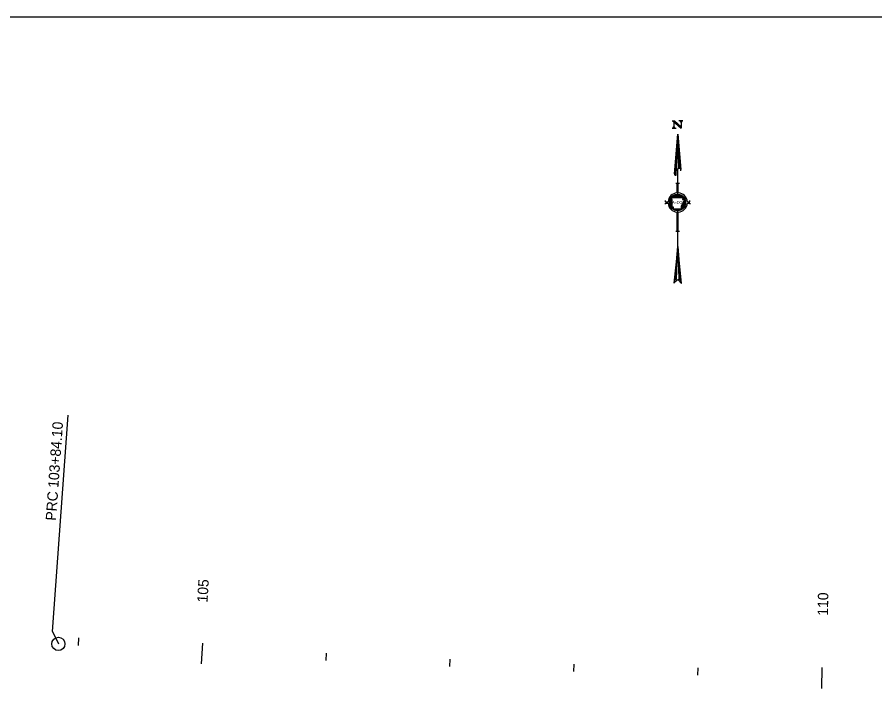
# Model space of a CAD drawing. Extents: x 1806834 to 1810084, y 678065 to 679314.
# Drawn here: x 1807616 to 1808308, y 678514 to 679065 of the extents above; entities that cross this region are included whole.
import ezdxf

# ---------------------------------------------------------------- set-up
doc = ezdxf.new("R2010")
doc.units = 0
for name, color, linetype in [('Default', 7, 'Continuous'), ('DSN_DRFT_Guideline-No-Plot', 7, 'Continuous'), ('DSN_RDWY_Alignment Annotation', 7, 'Continuous')]:
    doc.layers.add(name, color=color, linetype=linetype)

msp = doc.modelspace()

# ---------------------------------------------------------------- linework, layer by layer
at = {"layer": 'Default'}
for p, q in [((1808144.25, 678980.98), (1808146.02, 678980.98)), ((1808144.79, 678980.98), (1808151.47, 678975.04)), ((1808144.87, 678980.98), (1808151.47, 678975.12)), ((1808144.95, 678980.98), (1808151.47, 678975.17)), ((1808145.02, 678980.98), (1808151.47, 678975.25)), ((1808145.1, 678980.98), (1808151.47, 678975.3)), ((1808145.18, 678980.98), (1808151.47, 678975.38)), ((1808145.23, 678980.98), (1808151.47, 678975.43)), ((1808145.3, 678980.98), (1808151.47, 678975.5)), ((1808145.38, 678980.98), (1808151.47, 678975.56)), ((1808145.46, 678980.98), (1808151.47, 678975.63)), ((1808145.54, 678980.98), (1808151.47, 678975.71)), ((1808145.61, 678980.98), (1808151.47, 678975.76)), ((1808145.64, 678980.98), (1808145.64, 678975.04)), ((1808145.69, 678980.98), (1808151.47, 678975.84)), ((1808145.74, 678980.98), (1808151.47, 678975.89)), ((1808145.82, 678980.98), (1808151.47, 678975.97)), ((1808145.9, 678980.98), (1808151.47, 678976.02)), ((1808145.97, 678980.98), (1808151.47, 678976.1)), ((1808146.02, 678980.98), (1808151.47, 678976.12)), ((1808151.08, 678980.98), (1808149.59, 678980.98)), ((1808152.83, 678980.98), (1808151.08, 678980.98)), ((1808151.47, 678980.98), (1808151.47, 678975.04)), ((1808144.25, 678975.04), (1808146.02, 678975.04)), ((1808146.02, 678975.04), (1808147.51, 678975.04)), ((1808146.25, 678937.53), (1808146.25, 678938.3)), ((1808146.64, 678937.22), (1808146.64, 678939.07)), ((1808147, 678937.15), (1808147, 678939.61)), ((1808147.46, 678937.15), (1808147.46, 678940.77)), ((1808148.64, 678921.99), (1808148.64, 678941.93)), ((1808147.18, 678930.7), (1808148.16, 678930.7)), ((1808148.16, 678922.94), (1808148.16, 678930.7)), ((1808149.13, 678922.97), (1808149.13, 678930.7)), ((1808149.13, 678930.7), (1808150.11, 678930.7)), ((1808138.91, 678915.67), (1808138.91, 678916.65)), ((1808138.91, 678915.67), (1808140.87, 678915.67)), ((1808142.07, 678913.54), (1808142.07, 678916.77)), ((1808142.3, 678912.77), (1808142.3, 678917.52)), ((1808142.56, 678912.25), (1808142.56, 678918.08)), ((1808142.79, 678911.84), (1808142.79, 678918.52)), ((1808143.04, 678911.46), (1808143.04, 678918.91)), ((1808143.27, 678911.1), (1808143.27, 678919.29)), ((1808143.53, 678910.86), (1808143.53, 678919.6)), ((1808143.76, 678910.58), (1808143.76, 678919.83)), ((1808144.3, 678916.18), (1808143.84, 678919.16)), ((1808143.84, 678919.16), (1808152.73, 678919.16)), ((1808144.02, 678919.16), (1808144.02, 678920.09)), ((1808144.02, 678910.33), (1808144.02, 678917.93)), ((1808144.1, 678911.69), (1808144.3, 678916.18)), ((1808144.25, 678919.16), (1808144.25, 678920.29)), ((1808144.25, 678915.64), (1808144.25, 678916.31)), ((1808144.51, 678919.16), (1808144.51, 678920.52)), ((1808144.74, 678919.16), (1808144.74, 678920.7)), ((1808145, 678919.16), (1808145, 678920.86)), ((1808145.23, 678919.16), (1808145.23, 678921.01)), ((1808145.48, 678919.16), (1808145.48, 678921.14)), ((1808145.72, 678919.16), (1808145.72, 678921.27)), ((1808145.97, 678919.16), (1808145.97, 678921.37)), ((1808146.2, 678919.16), (1808146.2, 678921.48)), ((1808146.44, 678919.16), (1808146.44, 678921.58)), ((1808146.69, 678919.16), (1808146.69, 678921.65)), ((1808146.92, 678919.16), (1808146.92, 678921.73)), ((1808147.18, 678919.16), (1808147.18, 678921.78)), ((1808147.41, 678919.16), (1808147.41, 678921.84)), ((1808147.67, 678919.16), (1808147.67, 678921.86)), ((1808147.9, 678919.16), (1808147.9, 678921.91)), ((1808148.16, 678919.16), (1808148.16, 678921.94)), ((1808148.39, 678919.16), (1808148.39, 678921.96)), ((1808148.64, 678919.16), (1808148.64, 678921.99)), ((1808148.88, 678919.16), (1808148.88, 678921.94)), ((1808149.13, 678919.16), (1808149.13, 678921.94)), ((1808149.36, 678919.16), (1808149.36, 678921.89)), ((1808149.62, 678919.16), (1808149.62, 678921.86)), ((1808149.85, 678919.16), (1808149.85, 678921.81)), ((1808150.11, 678919.16), (1808150.11, 678921.76)), ((1808150.34, 678919.16), (1808150.34, 678921.71)), ((1808150.57, 678919.16), (1808150.57, 678921.63)), ((1808150.83, 678919.16), (1808150.83, 678921.55)), ((1808151.06, 678919.16), (1808151.06, 678921.48)), ((1808151.32, 678919.16), (1808151.32, 678921.37)), ((1808151.55, 678919.16), (1808151.55, 678921.27)), ((1808151.8, 678919.16), (1808151.8, 678921.14)), ((1808152.04, 678919.16), (1808152.04, 678921.01)), ((1808152.29, 678919.16), (1808152.29, 678920.86)), ((1808152.52, 678919.16), (1808152.52, 678920.68)), ((1808152.88, 678918.37), (1808152.55, 678917.67)), ((1808152.55, 678917.67), (1808154.07, 678917.67)), ((1808152.73, 678919.16), (1808152.73, 678919.16)), ((1808152.73, 678919.16), (1808152.93, 678918.8)), ((1808152.78, 678919.11), (1808152.78, 678920.52)), ((1808152.78, 678917.67), (1808152.78, 678918.11)), ((1808152.93, 678918.8), (1808152.88, 678918.37)), ((1808153.01, 678917.7), (1808153.01, 678920.29)), ((1808153.47, 678915.9), (1808153.19, 678915.1)), ((1808153.27, 678917.7), (1808153.27, 678920.11)), ((1808153.47, 678915.9), (1808153.73, 678916.54)), ((1808153.5, 678917.7), (1808153.5, 678919.86)), ((1808153.5, 678910.5), (1808153.5, 678915.93)), ((1808154.17, 678917.08), (1808153.73, 678916.54)), ((1808153.76, 678917.67), (1808153.76, 678919.6)), ((1808153.76, 678910.76), (1808153.76, 678916.54)), ((1808153.99, 678917.67), (1808153.99, 678919.34)), ((1808153.99, 678911.07), (1808153.99, 678916.85)), ((1808154.07, 678917.67), (1808154.27, 678917.42)), ((1808154.27, 678917.42), (1808154.17, 678917.08)), ((1808154.25, 678917.49), (1808154.25, 678918.98)), ((1808154.25, 678911.4), (1808154.25, 678917.24)), ((1808154.48, 678911.76), (1808154.48, 678918.57)), ((1808154.71, 678912.23), (1808154.71, 678918.14)), ((1808154.96, 678912.79), (1808154.96, 678917.57)), ((1808155.2, 678913.61), (1808155.2, 678916.8)), ((1808156.41, 678915.67), (1808158.36, 678915.67)), ((1808158.36, 678915.67), (1808158.36, 678916.65)), ((1808138.91, 678913.72), (1808138.91, 678914.69)), ((1808138.91, 678914.69), (1808140.87, 678914.69)), ((1808144.48, 678911.46), (1808144.1, 678911.69)), ((1808144.25, 678910.12), (1808144.25, 678911.56)), ((1808145.23, 678911.46), (1808144.48, 678911.46)), ((1808144.51, 678909.91), (1808144.51, 678911.43)), ((1808144.74, 678909.71), (1808144.74, 678911.43)), ((1808145, 678909.58), (1808145, 678911.43)), ((1808145.23, 678909.86), (1808145.23, 678911.46)), ((1808151.44, 678909.86), (1808145.23, 678909.86)), ((1808145.23, 678909.4), (1808145.23, 678909.84)), ((1808145.48, 678909.27), (1808145.48, 678909.86)), ((1808145.72, 678909.14), (1808145.72, 678909.86)), ((1808145.97, 678909.04), (1808145.97, 678909.86)), ((1808146.2, 678908.94), (1808146.2, 678909.86)), ((1808146.44, 678908.84), (1808146.44, 678909.86)), ((1808146.69, 678908.76), (1808146.69, 678909.86)), ((1808146.92, 678908.68), (1808146.92, 678909.86)), ((1808147.18, 678908.63), (1808147.18, 678909.86)), ((1808147.41, 678908.55), (1808147.41, 678909.86)), ((1808147.67, 678908.53), (1808147.67, 678909.86)), ((1808147.9, 678908.5), (1808147.9, 678909.86)), ((1808148.16, 678908.45), (1808148.16, 678909.86)), ((1808148.39, 678908.42), (1808148.39, 678909.86)), ((1808148.64, 678908.42), (1808148.64, 678909.86)), ((1808148.88, 678908.42), (1808148.88, 678909.86)), ((1808149.13, 678908.45), (1808149.13, 678909.86)), ((1808149.36, 678908.48), (1808149.36, 678909.86)), ((1808149.62, 678908.5), (1808149.62, 678909.86)), ((1808149.85, 678908.55), (1808149.85, 678909.86)), ((1808150.11, 678908.6), (1808150.11, 678909.86)), ((1808150.34, 678908.66), (1808150.34, 678909.86)), ((1808150.57, 678908.73), (1808150.57, 678909.86)), ((1808150.83, 678908.78), (1808150.83, 678909.86)), ((1808151.06, 678908.89), (1808151.06, 678909.86)), ((1808151.32, 678908.99), (1808151.32, 678909.86)), ((1808151.75, 678910.5), (1808151.44, 678909.86)), ((1808151.55, 678909.09), (1808151.55, 678909.99)), ((1808151.8, 678912.74), (1808151.65, 678911.56)), ((1808151.65, 678911.56), (1808151.75, 678910.5)), ((1808152.34, 678913.67), (1808151.8, 678912.74)), ((1808151.8, 678909.22), (1808151.8, 678912.53)), ((1808152.04, 678909.35), (1808152.04, 678913.05)), ((1808152.29, 678909.5), (1808152.29, 678913.49)), ((1808152.68, 678914.36), (1808152.34, 678913.67)), ((1808152.52, 678909.66), (1808152.52, 678913.97)), ((1808153.19, 678915.1), (1808152.68, 678914.36)), ((1808152.78, 678909.84), (1808152.78, 678914.44)), ((1808153.01, 678910.04), (1808153.01, 678914.8)), ((1808153.27, 678910.25), (1808153.27, 678915.28)), ((1808156.41, 678914.69), (1808158.36, 678914.69)), ((1808158.36, 678914.69), (1808158.36, 678913.72)), ((1808148.16, 678892.14), (1808148.16, 678907.42)), ((1808148.64, 678879.67), (1808148.64, 678908.37)), ((1808149.13, 678892.14), (1808149.13, 678907.42)), ((1808147.18, 678892.14), (1808148.16, 678892.14)), ((1808149.13, 678892.14), (1808150.11, 678892.14)), ((1808148.64, 678879.67), (1808145.58, 678850.16)), ((1808151.61, 678849.93), (1808148.64, 678879.67)), ((1808145.58, 678850.16), (1808148.64, 678853.21)), ((1808148.64, 678853.21), (1808151.61, 678849.93))]:
    msp.add_line(p, q, dxfattribs=at)
for points in [[(1808152.29, 678980.98), (1808151.47, 678979.95), (1808150.67, 678980.98), (1808150.8, 678980.93), (1808152.19, 678980.93), (1808151.47, 678980.03), (1808150.83, 678980.87), (1808152.11, 678980.9), (1808151.47, 678980.13), (1808150.93, 678980.82), (1808151.98, 678980.85), (1808151.47, 678980.21), (1808151.03, 678980.77), (1808151.86, 678980.8), (1808151.47, 678980.31), (1808151.16, 678980.72), (1808151.75, 678980.75), (1808151.47, 678980.39), (1808151.27, 678980.67), (1808151.62, 678980.69), (1808151.47, 678980.46), (1808151.37, 678980.64), (1808151.52, 678980.64), (1808151.47, 678980.54), (1808151.44, 678980.62), (1808151.47, 678980.62)], [(1808144.79, 678975.04), (1808145.64, 678976.07), (1808146.41, 678975.04), (1808146.31, 678975.09), (1808144.89, 678975.09), (1808145.61, 678975.99), (1808146.28, 678975.14), (1808145, 678975.12), (1808145.61, 678975.89), (1808146.18, 678975.2), (1808145.1, 678975.17), (1808145.61, 678975.81), (1808146.05, 678975.25), (1808145.25, 678975.22), (1808145.64, 678975.74), (1808145.92, 678975.3), (1808145.36, 678975.27), (1808145.61, 678975.63), (1808145.82, 678975.35), (1808145.46, 678975.32), (1808145.61, 678975.56), (1808145.72, 678975.38), (1808145.56, 678975.38), (1808145.61, 678975.48), (1808145.66, 678975.4), (1808145.64, 678975.4)], [(1808146.08, 678938.15), (1808148.64, 678970.16), (1808151.21, 678941.64)], [(1808146.69, 678940.59), (1808148.64, 678970.16), (1808150.7, 678942.9)], [(1808147.23, 678941.28), (1808148.64, 678970.16), (1808150.01, 678943.06)], [(1808148.03, 678942.13), (1808148.64, 678970.16), (1808149.24, 678942.98)], [(1808146.38, 678851.99), (1808148.64, 678879.67), (1808150.8, 678851.9)], [(1808150.12, 678852.66), (1808148.64, 678879.67), (1808147.07, 678852.67)], [(1808147.75, 678853.33), (1808148.64, 678879.67), (1808149.42, 678853.42)]]:
    msp.add_lwpolyline(points, dxfattribs=at)
for start, end in [(93.60728, 176.42391), (3.57609, 86.41459), (183.61351, 266.41233), (273.59889, 356.38649)]:
    msp.add_arc((1808148.64, 678915.18), 7.79, start, end, dxfattribs=at)
for start_param, end_param in [(5.778782, 6.897374), (2.681637, 5.778782), (2.292506, 2.677814)]:
    msp.add_ellipse((1808148.64, 678939.84), major_axis=(-2.28, -2.53), ratio=0.467585, start_param=start_param, end_param=end_param, dxfattribs=at)
at = {"layer": 'DSN_DRFT_Guideline-No-Plot'}
msp.add_lwpolyline([(1806833.89, 678065.46), (1808483.89, 678065.46), (1808483.89, 679064.52), (1806833.89, 679064.52)], close=True, dxfattribs=at)
at = {"layer": 'DSN_RDWY_Alignment Annotation'}
for p, q in [((1807644.79, 678569.6), (1807657.27, 678743.82)), ((1807644.79, 678569.6), (1807649.44, 678559.44)), ((1807665.72, 678564.3), (1807665.3, 678558.32)), ((1807649.44, 678559.44), (1807649.44, 678559.44)), ((1807765.6, 678560.13), (1807764.57, 678543.37)), ((1807865.23, 678552.04), (1807864.92, 678546.05)), ((1807965.07, 678547.22), (1807964.8, 678541.23)), ((1808064.93, 678543.27), (1808064.72, 678537.27)), ((1808164.83, 678540.19), (1808164.68, 678534.19)), ((1808264.8, 678540.38), (1808264.5, 678523.58))]:
    msp.add_line(p, q, dxfattribs=at)
msp.add_circle((1807649.44, 678559.44), 5.34, dxfattribs=at)

# ---------------------------------------------------------------- texts
at = {"layer": 'Default'}
for s, height, p in [('A  DOT', 2.179, (1808144.22, 678914.08)), ('R', 1.45, (1808146.16, 678914.08))]:
    msp.add_text(s, height=height, dxfattribs=at).set_placement(p)
at = {"layer": 'DSN_RDWY_Alignment Annotation'}
for s, rotation, p in [('103+84.10', 85.90455, (1807649.44, 678684.98)), ('PRC', 85.90455, (1807647.55, 678658.54)), ('105', 86.48404, (1807769.62, 678592.65)), ('110', 88.98404, (1808269.74, 678582.13))]:
    msp.add_text(s, height=8.4, rotation=rotation, dxfattribs=at).set_placement(p)

doc.saveas('drawing.dxf')
